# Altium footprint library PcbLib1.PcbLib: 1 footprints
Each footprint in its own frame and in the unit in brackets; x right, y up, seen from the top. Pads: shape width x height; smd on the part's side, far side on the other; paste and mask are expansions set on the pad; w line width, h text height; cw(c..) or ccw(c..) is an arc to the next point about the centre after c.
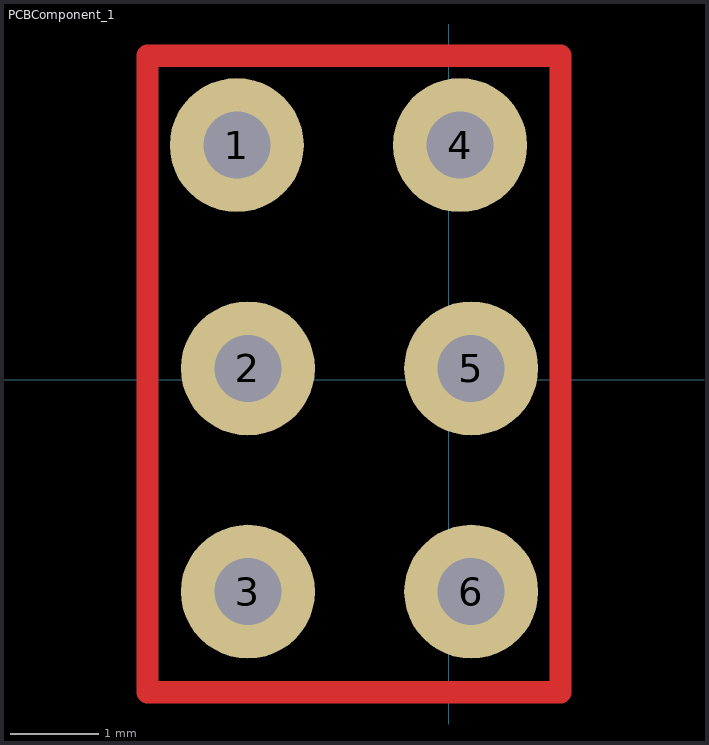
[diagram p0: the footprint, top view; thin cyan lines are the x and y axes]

## PCBComponent_1 [mil]
pads (6):
  round 60 hole 30: 1(-95,105) 2(-90,5) 3(-90,-95) 4(5,105) 5(10,5) 6(10,-95)
Top Layer:
  lines w10: -135,-140 50,-140 50,145 -135,145 -135,-140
